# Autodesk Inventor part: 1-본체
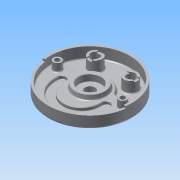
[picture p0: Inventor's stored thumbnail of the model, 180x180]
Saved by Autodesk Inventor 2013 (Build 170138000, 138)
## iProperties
Created: 2015-06
Part Number: 1-본체
Material: 알루미늄 6061
Document SubType Name: Modeling
Designer: Administrator
Density: 1 g/cm^3
Author: Administrator
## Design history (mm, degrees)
sketch "스케치1"
  geometry: C1 r 95 at (0, 0); 1 further point
  constraints: 1 centre point, 1 coincident
  dimensions: "d0" = 190 diameter of C1
extrude "돌출1" new body sketch "스케치1" distance "d2" = 32; taper "d3" = 0 deg
feature "쉘1" dims "d4" = 14, "d5" = 5
sketch "스케치2"
  geometry: C1 r 90 at (0, 0) reference; C2 r 35 at (0, 0)
  constraints: 1 centre point, 1 coincident
  dimensions: "d6" = 70 diameter of C2
extrude "돌출2" join sketch "스케치2" distance "d8" = 10; taper "d9" = -10 deg
sketch "스케치3"
  geometry: L1 (45.033, 16)-(75.657, 16); L2 (-45.033, 16)-(-75.657, 16); C1 r 35 at (0, 0) reference; C2 r 90 at (0, 0) reference; A1 r 42 centre (0, 0) between (36.373, 21) and (-36.373, 21); A2 r 10 centre (-75.657, 26) between (-85.114, 29.25) and (-75.657, 16); A3 r 10 centre (75.657, 26) between (75.657, 16) and (85.114, 29.25); A4 r 90 centre (0, 0) between (-85.114, 29.25) and (85.114, 29.25) reference; A5 r 10 centre (-45.033, 26) between (-45.033, 16) and (-36.373, 21); A6 r 10 centre (45.033, 26) between (36.373, 21) and (45.033, 16)
  constraints: 12 point on circle, 8 tangent, 5 centre point, 4 end point, 2 collinear, 2 equal radius, 1 coincident, 1 horizontal
  dimensions: "d10" = 84 diameter of A1; "d12" = 16 distance from line of L1 C1.centre; "d13" = 10 radius of A2; "d14" = 10 radius of A5
extrude "돌출3" cut sketch "스케치3" distance "d15" = 7; taper "d16" = 0 deg
sketch "스케치4"
  geometry: L1 (-59, -19)-(-59, -14); L2 (-41, -19)-(-41, -14); L3 (41, -19)-(41, -14); L4 (59, -19)-(59, -14); A1 r 90 centre (0, 0) between (-85.114, 29.25) and (85.114, 29.25) reference; A2 r 9 centre (-50, -19) between (-59, -19) and (-41, -19); A3 r 9 centre (50, -19) between (59, -19) and (41, -19); A4 r 41 centre (0, -19) between (-41, -19) and (41, -19); A5 r 9 centre (-50, -14) between (-59, -14) and (-41, -14); A6 r 9 centre (50, -14) between (41, -14) and (59, -14); A7 r 59 centre (0, -19) between (-59, -19) and (59, -19)
  constraints: 12 point on circle, 9 tangent, 8 end point, 6 centre point, 3 equal radius, 3 vertical alignment, 2 horizontal alignment, 1 coincident
  dimensions: "d36" = 19 distance of A7.centre A1.centre; "d38" = 41 radius of A4; "d39" = 5 distance of A2.centre A5.centre; "d40" = 59 radius of A7
extrude "돌출4" cut sketch "스케치4" distance "d21" = 7; taper "d22" = 0 deg
sketch "스케치5"
  geometry: L1 (-45.033, 16)-(-75.657, 16) reference; L2 (-74, 0)-(74, 0); C1 r 9 at (-74, 0); C2 r 9 at (74, 0); A1 r 90 centre (0, 0) between (-85.114, 29.25) and (85.114, 29.25) reference; 1 further point
  constraints: 2 centre point, 2 end point, 2 horizontal alignment, 1 coincident, 1 equal radius, 1 midpoint, 1 parallel
  dimensions: "d23" = 18 diameter of C1; "d25" = 148 distance of L2.end L2.start
extrude "돌출5" join sketch "스케치5" stored distance "d26" = 7; taper "d27" = 0 deg
sketch "스케치6"
  geometry: L1 (-45.033, 16)-(-75.657, 16) reference; L2 (-40, 52)-(40, 52); C1 r 15 at (-40, 52); C2 r 15 at (40, 52); C3 r 10 at (-40, 52); C4 r 10 at (40, 52); A1 r 90 centre (0, 0) between (85.114, 29.25) and (-85.114, 29.25) reference; 1 further point
  constraints: 4 centre point, 2 coincident, 2 end point, 2 equal radius, 1 horizontal alignment, 1 midpoint, 1 parallel, 1 vertical alignment
  dimensions: "d28" = 30 diameter of C1; "d30" = 52 vertical distance of L2.end A1.centre; "d31" = 80 distance of L2.end L2.start; "d32" = 20 diameter of C3
extrude "돌출6" join sketch "스케치6" stored distance "d33" = 0; taper "d34" = 0 deg
sketch "스케치7"
  geometry: C1 r 9 at (-74, 0) reference; C2 r 9 at (74, 0) reference; 2 further points
  constraints: 2 coincident
hole "구멍1" sketch "스케치7" at (-74, 0), (74, 0) diameter "d41" = 11; stored, may be unused: countersink angle "d45" = 90 deg, drill point angle "d47" = 118 deg; dims "d42" = 6, "d43" = 18, "d44" = 11, "d46" = 8
hole "구멍2" diameter "d50" = 23; stored, may be unused: countersink angle "d54" = 90 deg, drill point angle "d56" = 118 deg; dims "d48" = 10, "d49" = 10, "d51" = 6, "d52" = 50, "d53" = 15, "d55" = 8
extrude "돌출7" cut sketch "스케치6" stored distance "d57" = 7; taper "d58" = 0 deg
sketch "스케치9"
  geometry: C1 r 95 at (0, 0) reference; C2 r 68 at (0, 0)
  constraints: 1 centre point, 1 coincident, 1 other
  dimensions: "d64" = 136 diameter of C2
feature "엠보싱1" sketch "스케치9" dims "d10" = 84, "d12" = 16, "d13" = 10, "d14" = 10, "d66" = 0.5, "d67" = 0
chamfer "모따기1" distance "d68" = 1; stored, may be unused: second distance "d69" = 2, angle "d70" = 45 deg
sketch "스케치10"
  geometry: L1 (-6, 13.748)-(-6, -13.748); L2 (6, 13.748)-(6, -13.748); L3 (66.252, 6)-(93.748, 6); L4 (66.252, -6)-(93.748, -6); C1 r 10 at (80, 0) reference; A1 r 15 centre (0, 0) between (-6, 13.748) and (-6, -13.748) reference; A2 r 15 centre (80, 0) between (66.252, 6) and (93.748, 6) reference; 1 further point
  constraints: 8 end point, 8 point on circle, 4 parallel, 1 perpendicular, 1 vertical
  dimensions: "d71" = 12 distance between parallel lines of L2 L1; "d72" = 12 distance between parallel lines of L4 L3
extrude "돌출9" cut sketch "스케치10" distance "d73" = 3; taper "d74" = 0 deg
fillet "모깎기1" dims "d75" = 3
fillet "모깎기2" dims "d76" = 3
sketch "스케치11"
  geometry: C1 r 11.5 at (0, 0) reference; C2 r 26 at (0, 0)
  constraints: 1 centre point, 1 coincident
  dimensions: "d77" = 52 diameter of C2
extrude "돌출10" join sketch "스케치11" distance "d79" = 12; taper "d80" = -15 deg
fillet "모깎기3" dims "d81" = 5
hole "구멍3" diameter "d84" = 23; stored, may be unused: countersink angle "d88" = 90 deg, drill point angle "d90" = 118 deg; dims "d82" = 10, "d83" = 10, "d85" = 6, "d86" = 4, "d87" = 2, "d89" = 8
chamfer "모따기2" distance "d91" = 1; stored, may be unused: second distance "d92" = 2, angle "d93" = 45 deg
fillet "모깎기4" dims "d94" = 1
fillet "모깎기5" dims "d95" = 3
fillet "모깎기6" dims "d96" = 0.3
sketch "스케치12"
  geometry: L1 (0, 0)-(-89.124, -12.526); L2 (0, 0)-(89.124, -12.526); L3 (-95, 0)-(95, 0); L4 (-89.124, -12.526)-(-94.075, -13.221); L5 (89.124, -12.526)-(94.075, -13.221); A1 r 90 centre (0, 0) between (-89.124, -12.526) and (89.124, -12.526) reference; A2 r 95 centre (0, 0) between (-94.075, -13.221) and (94.075, -13.221) reference
  constraints: 10 end point, 6 point on circle, 2 collinear, 1 horizontal, 1 midpoint
  dimensions: "d97" = 8 deg angle of L1 L3; "d98" = 8 deg angle of L3 L2
extrude "돌출11" cut sketch "스케치12" distance "d99" = 5; taper "d100" = 0 deg
node "솔리드1"
other parameters: "d37" = 59
